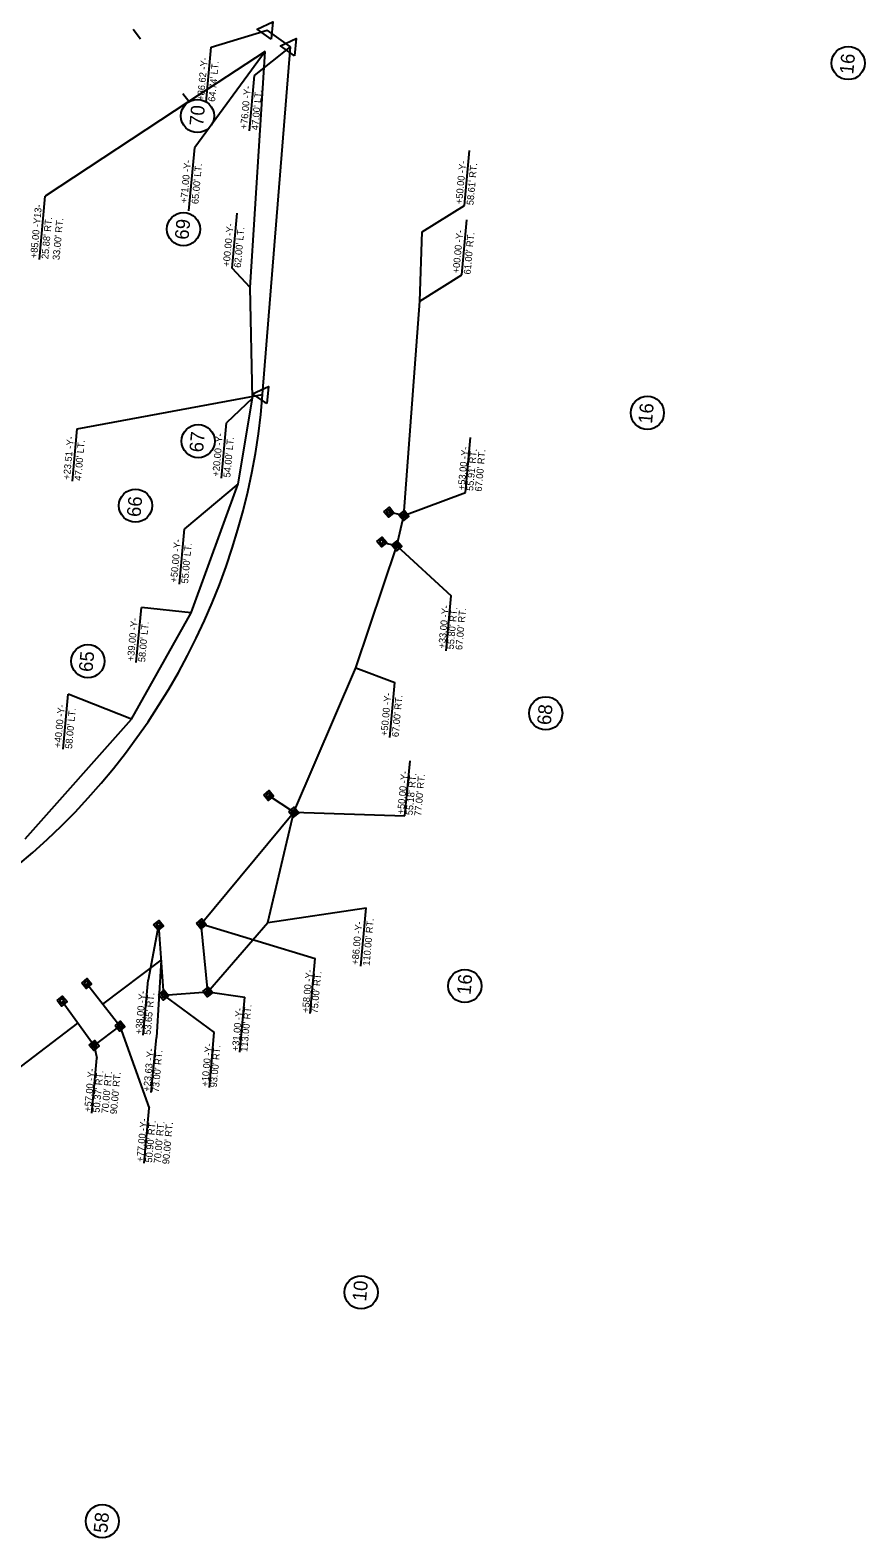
# Model space of a CAD drawing. Extents: x 2010883 to 2014849, y 442000 to 447413.
# Drawn here: x 2012411 to 2013014, y 445530 to 446621 of the extents above; entities that cross this region are included whole.
import ezdxf

# ---------------------------------------------------------------- set-up
doc = ezdxf.new("R2010")
doc.units = 0
for name, color, linetype in [('Prop Easement Construction', 7, 'Continuous'), ('Prop Easement Construction Station Offsets', 7, 'Continuous'), ('Prop Easement Permanent Drainage', 7, 'Continuous'), ('Prop Easement Permanent Drainage Station Offsets', 7, 'Continuous'), ('Prop Parcel Number CELL', 7, 'Continuous'), ('Prop Parcel Number Text', 7, 'Continuous'), ('Prop ROW Marker CELL', 7, 'Continuous'), ('Prop ROW Permanent Easement CELL', 7, 'Continuous'), ('Prop ROW RW Lines', 7, 'Continuous'), ('Prop ROW Station Offsets', 7, 'Continuous')]:
    doc.layers.add(name, color=color, linetype=linetype)

msp = doc.modelspace()

# ---------------------------------------------------------------- linework, layer by layer
at = {"layer": 'Prop Easement Construction'}
for p, q in [((2012490.7, 446614.3), (2012485.3, 446621.3)), ((2012580.7, 446605.3), (2012525.6, 446569.1)), ((2012570, 446434.6), (2012580.7, 446605.3)), ((2012525.6, 446569.1), (2012521.3, 446574.7)), ((2012692.6, 446424.8), (2012694.3, 446474.8)), ((2012571.7, 446354.5), (2012570, 446434.6)), ((2012681.1, 446269.7), (2012692.6, 446424.8)), ((2012561.2, 446292.5), (2012571.7, 446354.5)), ((2012581, 446351.2), (2012580.2, 446351.5)), ((2012527.3, 446199.2), (2012561.2, 446292.5)), ((2012646.3, 446159.4), (2012676, 446247.8)), ((2012484, 446122.3), (2012527.3, 446199.2)), ((2012601.4, 446055), (2012646.3, 446159.4)), ((2012407.2, 446035.7), (2012484, 446122.3)), ((2012582.6, 445975.3), (2012601.4, 446055)), ((2012463.4, 445916.1), (2012505.5, 445948.1)), ((2012354.2, 445832.8), (2012445.4, 445902.5)), ((2012445.4, 445902.5), (2012445.4, 445902.5))]:
    msp.add_line(p, q, dxfattribs=at)
msp.add_lwpolyline([(2012539.3, 445925), (2012582.6, 445975.3)], dxfattribs=at)
at = {"layer": 'Prop Easement Construction Station Offsets'}
for p, q in [((2012580.7, 446605.3), (2012529.8, 446536)), ((2012525.6, 446569.1), (2012421.8, 446500.7)), ((2012525.6, 446490.1), (2012529.8, 446536)), ((2012724.9, 446493.9), (2012728.6, 446533.7)), ((2012417.6, 446454.9), (2012421.8, 446500.7)), ((2012556.8, 446448.6), (2012560.4, 446488.4)), ((2012694.3, 446474.8), (2012724.9, 446493.9)), ((2012722.9, 446443.8), (2012726.6, 446483.6)), ((2012570, 446434.6), (2012556.8, 446448.6)), ((2012692.6, 446424.8), (2012722.9, 446443.8)), ((2012571.7, 446354.5), (2012552.8, 446336.7)), ((2012549.2, 446296.8), (2012552.8, 446336.7)), ((2012561.2, 446292.5), (2012522.4, 446260)), ((2012518.7, 446220.1), (2012522.4, 446260)), ((2012487.6, 446163.3), (2012491.3, 446203.1)), ((2012527.3, 446199.2), (2012491.3, 446203.1)), ((2012646.3, 446159.4), (2012674.5, 446148.9)), ((2012670.9, 446109.1), (2012674.5, 446148.9)), ((2012434.7, 446100.6), (2012438.4, 446140.4)), ((2012484, 446122.3), (2012438.4, 446140.4)), ((2012582.6, 445975.3), (2012653.7, 445985.9)), ((2012649.9, 445943.6), (2012653.7, 445985.9))]:
    msp.add_line(p, q, dxfattribs=at)
at = {"layer": 'Prop Easement Permanent Drainage'}
for p, q in [((2012681.1, 446269.7), (2012670.2, 446272)), ((2012676, 446247.8), (2012681.1, 446269.7)), ((2012665.1, 446250.5), (2012676, 446247.8)), ((2012601.4, 446055), (2012583.2, 446067.1)), ((2012534.6, 445974.2), (2012601.4, 446055)), ((2012503.7, 445973.2), (2012507.3, 445922.7)), ((2012534.6, 445974.2), (2012534.6, 445974.2)), ((2012539.3, 445925), (2012534.6, 445974.2)), ((2012475.8, 445900.3), (2012451.7, 445931.1)), ((2012433.9, 445918.4), (2012457.1, 445886.3)), ((2012507.3, 445922.7), (2012539.3, 445925)), ((2012457.1, 445886.3), (2012475.8, 445900.3))]:
    msp.add_line(p, q, dxfattribs=at)
at = {"layer": 'Prop Easement Permanent Drainage Station Offsets'}
for p, q in [((2012725.6, 446286.3), (2012729.2, 446326.2)), ((2012681.1, 446269.7), (2012725.6, 446286.3)), ((2012676, 446247.8), (2012715.2, 446211.5)), ((2012711.5, 446171.7), (2012715.2, 446211.5)), ((2012681.8, 446052.5), (2012685.5, 446092.3)), ((2012601.4, 446055), (2012681.8, 446052.5)), ((2012503.7, 445973.2), (2012496.2, 445933.6)), ((2012534.6, 445974.2), (2012616.9, 445949.1)), ((2012505.5, 445948.1), (2012502.1, 445892)), ((2012613.2, 445909.3), (2012616.9, 445949.1)), ((2012492.5, 445893.8), (2012496.2, 445933.6)), ((2012507.3, 445922.7), (2012544, 445895.6)), ((2012539.3, 445925), (2012566.1, 445921.3)), ((2012562.4, 445881.5), (2012566.1, 445921.3)), ((2012475.8, 445900.3), (2012496.9, 445841)), ((2012457.1, 445886.3), (2012459.1, 445877.1)), ((2012498.4, 445852.2), (2012502.1, 445892)), ((2012540.4, 445855.8), (2012544, 445895.6)), ((2012455.5, 445837.3), (2012459.1, 445877.1)), ((2012493.2, 445801.2), (2012496.9, 445841))]:
    msp.add_line(p, q, dxfattribs=at)
at = {"layer": 'Prop Parcel Number CELL'}
for p, q in [((2013002.3, 446597), (2013002.3, 446597)), ((2012531.8, 446558.7), (2012531.8, 446558.7)), ((2012521.7, 446476.8), (2012521.7, 446476.8)), ((2012857.1, 446343.9), (2012857.1, 446343.9)), ((2012532.3, 446323.5), (2012532.3, 446323.5)), ((2012487, 446276.8), (2012487, 446276.8)), ((2012452.6, 446164.3), (2012452.6, 446164.3)), ((2012783.6, 446126.6), (2012783.6, 446126.6)), ((2012725.1, 445929.3), (2012725.1, 445929.3)), ((2012650.1, 445707.7), (2012650.1, 445707.7)), ((2012463, 445542.1), (2012463, 445542.1))]:
    msp.add_line(p, q, dxfattribs=at)
for centre in [(2013002.3, 446597), (2012531.8, 446558.7), (2012521.7, 446476.8), (2012857.1, 446343.9), (2012532.3, 446323.5), (2012487, 446276.8), (2012452.6, 446164.3), (2012783.6, 446126.6), (2012725.1, 445929.3), (2012650.1, 445707.7), (2012463, 445542.1)]:
    msp.add_circle(centre, 12, dxfattribs=at)
at = {"layer": 'Prop ROW Marker CELL'}
for p, q in [((2012599, 446608.8), (2012599, 446608.8)), ((2012578.9, 446357.1), (2012578.9, 446357.1)), ((2012670.2, 446272), (2012670.2, 446272)), ((2012681.1, 446269.7), (2012681.1, 446269.7)), ((2012665.1, 446250.5), (2012665.1, 446250.5)), ((2012676, 446247.8), (2012676, 446247.8)), ((2012583.2, 446067.1), (2012583.2, 446067.1)), ((2012601.4, 446055), (2012601.4, 446055)), ((2012503.7, 445973.2), (2012503.7, 445973.2)), ((2012534.6, 445974.2), (2012534.6, 445974.2)), ((2012451.7, 445931.1), (2012451.7, 445931.1)), ((2012433.9, 445918.4), (2012433.9, 445918.4)), ((2012507.3, 445922.7), (2012507.3, 445922.7)), ((2012539.3, 445925), (2012539.3, 445925)), ((2012475.8, 445900.3), (2012475.8, 445900.3)), ((2012457.1, 445886.3), (2012457.1, 445886.3))]:
    msp.add_line(p, q, dxfattribs=at)
for points in [[(2012585.2, 446614.2), (2012575, 446621.5), (2012586.3, 446626.7)], [(2012602, 446602.2), (2012591.9, 446609.5), (2012603.2, 446614.7)], [(2012581.9, 446350.6), (2012571.7, 446357.8), (2012583.1, 446363)]]:
    msp.add_lwpolyline(points, close=True, dxfattribs=at)
at = {"layer": 'Prop ROW Permanent Easement CELL'}
for points in [[(2012666.6, 446272.3), (2012670.6, 446275.6), (2012673.8, 446271.6), (2012669.9, 446268.4)], [(2012668.4, 446272.1), (2012670.4, 446273.8), (2012672, 446271.8), (2012670.1, 446270.2)], [(2012677.5, 446270), (2012681.4, 446273.2), (2012684.7, 446269.3), (2012680.7, 446266.1)], [(2012679.3, 446269.8), (2012681.2, 446271.4), (2012682.9, 446269.5), (2012680.9, 446267.9)], [(2012661.5, 446250.8), (2012665.4, 446254.1), (2012668.7, 446250.2), (2012664.8, 446246.9)], [(2012663.3, 446250.7), (2012665.3, 446252.3), (2012666.9, 446250.3), (2012665, 446248.7)], [(2012672.4, 446248.1), (2012676.3, 446251.3), (2012679.6, 446247.4), (2012675.6, 446244.2)], [(2012674.2, 446247.9), (2012676.1, 446249.6), (2012677.8, 446247.6), (2012675.8, 446246)], [(2012579.7, 446067.4), (2012583.6, 446070.7), (2012586.8, 446066.8), (2012582.9, 446063.5)], [(2012581.4, 446067.3), (2012583.4, 446068.9), (2012585, 446066.9), (2012583.1, 446065.3)], [(2012597.8, 446055.4), (2012601.7, 446058.6), (2012605, 446054.7), (2012601.1, 446051.5)], [(2012599.6, 446055.2), (2012601.6, 446056.8), (2012603.2, 446054.9), (2012601.2, 446053.2)], [(2012500.1, 445973.5), (2012504.1, 445976.8), (2012507.3, 445972.8), (2012503.4, 445969.6)], [(2012501.9, 445973.3), (2012503.9, 445975), (2012505.5, 445973), (2012503.6, 445971.4)], [(2012531.1, 445974.5), (2012535, 445977.8), (2012538.2, 445973.9), (2012534.3, 445970.6)], [(2012532.8, 445974.4), (2012534.8, 445976), (2012536.4, 445974.1), (2012534.5, 445972.4)], [(2012448.1, 445931.4), (2012452, 445934.7), (2012455.2, 445930.8), (2012451.3, 445927.5)], [(2012449.9, 445931.3), (2012451.8, 445932.9), (2012453.5, 445930.9), (2012451.5, 445929.3)], [(2012430.3, 445918.7), (2012434.2, 445922), (2012437.5, 445918), (2012433.5, 445914.8)], [(2012432.1, 445918.5), (2012434, 445920.2), (2012435.7, 445918.2), (2012433.7, 445916.6)], [(2012503.7, 445923), (2012507.7, 445926.3), (2012510.9, 445922.4), (2012507, 445919.1)], [(2012505.5, 445922.9), (2012507.5, 445924.5), (2012509.1, 445922.6), (2012507.2, 445920.9)], [(2012535.7, 445925.3), (2012539.6, 445928.5), (2012542.9, 445924.6), (2012538.9, 445921.4)], [(2012537.5, 445925.1), (2012539.4, 445926.8), (2012541.1, 445924.8), (2012539.1, 445923.2)], [(2012472.2, 445900.6), (2012476.1, 445903.9), (2012479.3, 445900), (2012475.4, 445896.7)], [(2012474, 445900.5), (2012475.9, 445902.1), (2012477.6, 445900.2), (2012475.6, 445898.5)], [(2012453.5, 445886.6), (2012457.5, 445889.9), (2012460.7, 445886), (2012456.8, 445882.7)], [(2012455.3, 445886.4), (2012457.3, 445888.1), (2012458.9, 445886.1), (2012457, 445884.5)]]:
    msp.add_lwpolyline(points, close=True, dxfattribs=at)
at = {"layer": 'Prop ROW RW Lines'}
for p, q in [((2012599, 446608.8), (2012582.2, 446620.8)), ((2012578.9, 446357.1), (2012599, 446608.8))]:
    msp.add_line(p, q, dxfattribs=at)
msp.add_arc((2012087.5, 446396.4), 493, 303.0111, 355.4266, dxfattribs=at)
at = {"layer": 'Prop ROW Station Offsets'}
for p, q in [((2012541.8, 446608.5), (2012582.2, 446620.8)), ((2012538.2, 446568.7), (2012541.8, 446608.5)), ((2012573, 446587.9), (2012599, 446608.8)), ((2012569.4, 446548), (2012573, 446587.9)), ((2012444.9, 446332.4), (2012578.9, 446357.1)), ((2012441.4, 446294.5), (2012444.9, 446332.4))]:
    msp.add_line(p, q, dxfattribs=at)

# ---------------------------------------------------------------- texts
at = {"layer": 'Prop Easement Construction Station Offsets'}
for s, p in [('+71.00 -Y-', (2012524.3, 446495.5)), ("65.00' LT.", (2012532.4, 446494.8)), ('+50.00 -Y-', (2012723.2, 446494.8)), ("58.61' RT.", (2012731.3, 446494)), ('+85.00 -Y13-', (2012415.8, 446455.7)), ("25.88' RT.", (2012423.9, 446455)), ("33.00' RT.", (2012432, 446454.3)), ('+00.00 -Y-', (2012555, 446449.5)), ("62.00' LT.", (2012563.1, 446448.7)), ('+00.00 -Y-', (2012721.1, 446444.7)), ("61.00' RT.", (2012729.2, 446443.9)), ('+20.00 -Y-', (2012547.4, 446297.7)), ("54.00' LT.", (2012555.5, 446297)), ('+50.00 -Y-', (2012517, 446221)), ("55.00' LT.", (2012525, 446220.3)), ('+39.00 -Y-', (2012485.8, 446164.1)), ("58.00' LT.", (2012493.9, 446163.4)), ('+50.00 -Y-', (2012669.1, 446110)), ("67.00' RT.", (2012677.2, 446109.2)), ('+40.00 -Y-', (2012433, 446101.5)), ("58.00' LT.", (2012441.1, 446100.7)), ('+86.00 -Y-', (2012648.1, 445944.5)), ("110.00' RT.", (2012656.2, 445943.8))]:
    msp.add_text(s, height=5, rotation=84.7467, dxfattribs=at).set_placement(p)
at = {"layer": 'Prop Easement Permanent Drainage Station Offsets'}
for s, p in [('+53.00 -Y-', (2012724.9, 446287.9)), ("55.91' RT.", (2012731.1, 446287.3)), ("67.00' RT.", (2012737.3, 446286.8)), ('+33.00 -Y-', (2012710.8, 446173.3)), ("55.80' RT.", (2012717, 446172.7)), ("67.00' RT.", (2012723.2, 446172.2)), ('+50.00 -Y-', (2012681.1, 446053.3)), ("55.18' RT.", (2012687.3, 446052.7)), ("77.00' RT.", (2012693.5, 446052.1)), ('+58.00 -Y-', (2012612.3, 445909.8)), ("75.00' RT.", (2012618.6, 445909.3)), ('+38.00 -Y-', (2012491.7, 445894.3)), ("53.65' RT.", (2012497.9, 445893.8)), ('+31.00 -Y-', (2012561.6, 445882)), ("113.00' RT.", (2012567.8, 445881.5)), ('+10.00 -Y-', (2012539.5, 445856.3)), ("93.00' RT.", (2012545.7, 445855.8)), ('+23.63 -Y-', (2012497.5, 445852.7)), ("73.00' RT.", (2012503.8, 445852.2)), ('+57.00 -Y-', (2012454.8, 445838.1)), ("50.37' RT.", (2012461, 445837.5)), ("70.00' RT.", (2012467.3, 445836.9)), ("90.00' RT.", (2012473.5, 445836.4)), ('+77.00 -Y-', (2012492.6, 445801.9)), ("50.90' RT.", (2012498.9, 445801.4)), ("70.00' RT.", (2012505.1, 445800.8)), ("90.00' RT.", (2012511.3, 445800.2))]:
    msp.add_text(s, height=5, rotation=84.7467, dxfattribs=at).set_placement(p)
at = {"layer": 'Prop Parcel Number Text'}
for s, p in [('16', (2013005.9, 446588.6)), ('70', (2012535.9, 446551.2)), ('69', (2012525.3, 446468.9)), ('16', (2012860.4, 446335.7)), ('67', (2012535.8, 446315.1)), ('66', (2012490.6, 446268.3)), ('65', (2012455.9, 446156.2)), ('68', (2012787.2, 446117.8)), ('16', (2012729.2, 445922.6)), ('10', (2012653.7, 445700.9)), ('58', (2012466.6, 445533.3))]:
    msp.add_text(s, height=10, rotation=84.7467, dxfattribs=at).set_placement(p)
at = {"layer": 'Prop ROW Station Offsets'}
for s, p in [('+86.62 -Y-', (2012536.4, 446569.6)), ("64.74' LT.", (2012544.5, 446568.8)), ('+76.00 -Y-', (2012567.6, 446548.9)), ("47.00' LT.", (2012575.7, 446548.2)), ('+23.51 -Y-', (2012439.6, 446295.4)), ("47.00' LT.", (2012447.7, 446294.7))]:
    msp.add_text(s, height=5, rotation=84.7467, dxfattribs=at).set_placement(p)

doc.saveas('drawing.dxf')
